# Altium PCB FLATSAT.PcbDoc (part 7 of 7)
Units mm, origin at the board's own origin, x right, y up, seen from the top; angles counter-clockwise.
Board outline 430 x 350 mm, 5 copper layers (Top Layer, Internal Plane 1, Internal Plane 2, DELETEME, Bottom Layer); 808 components, 852 nets, 6407 pads, 939 vias.
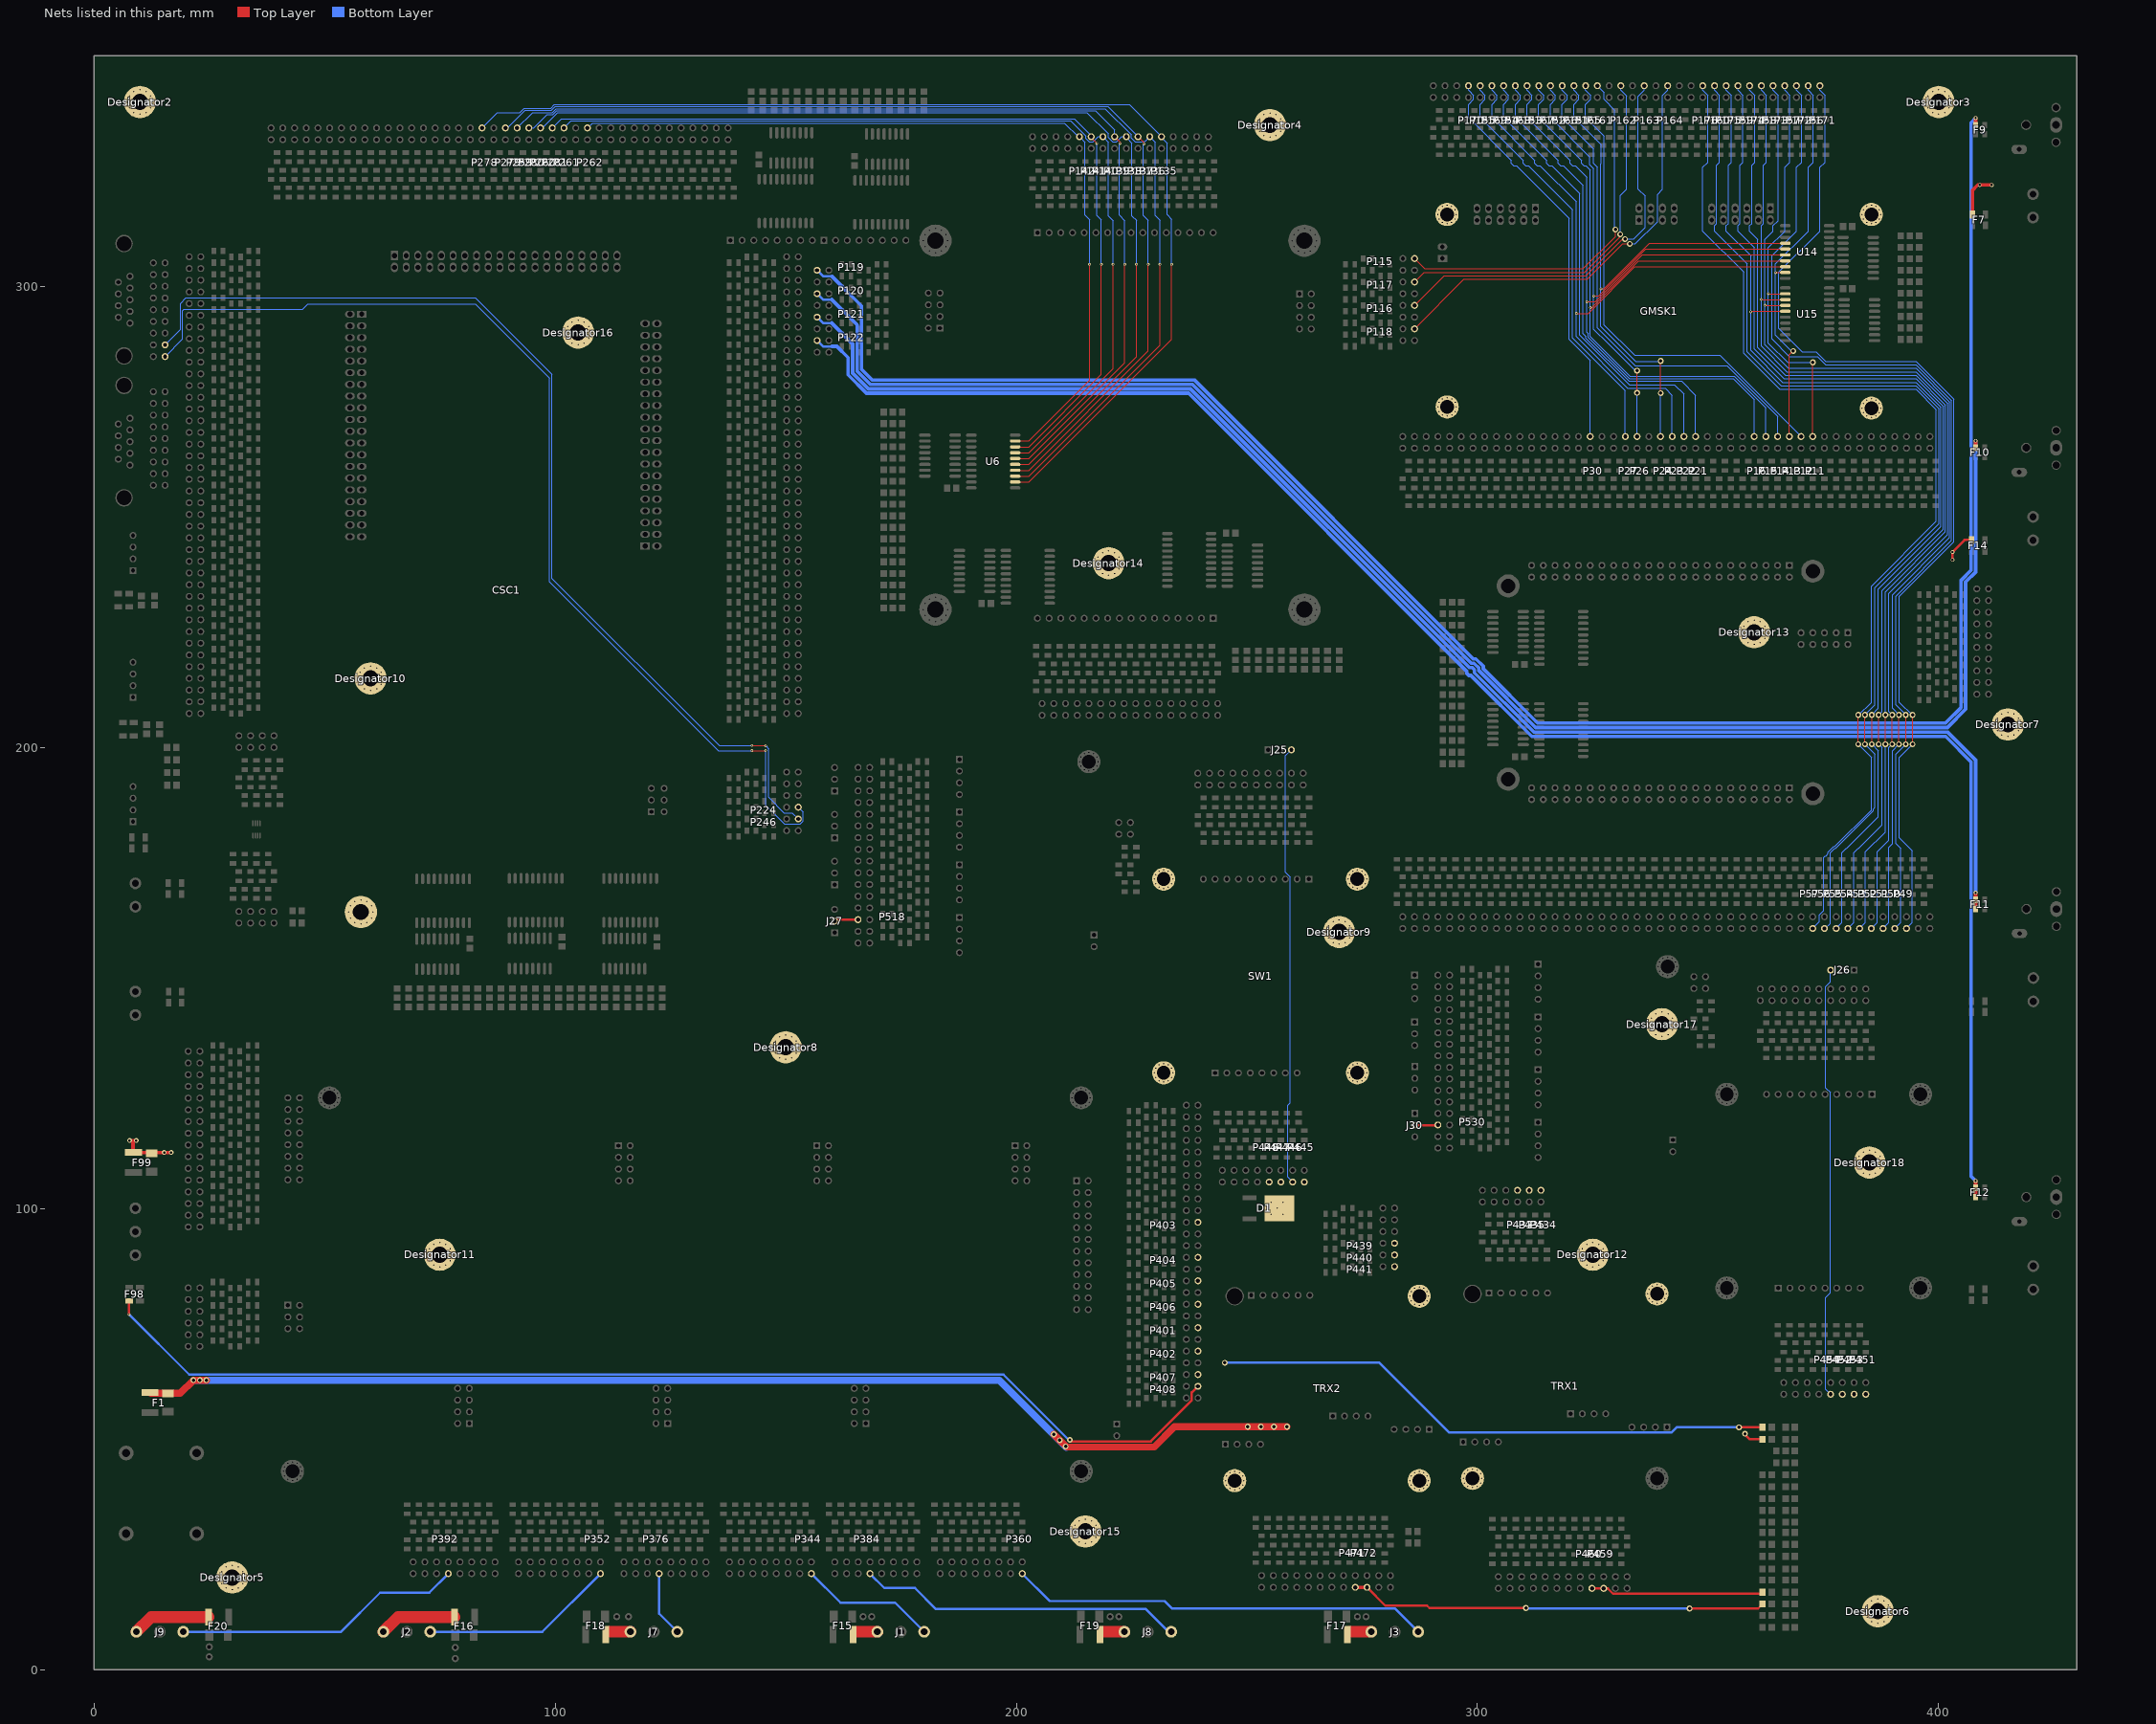
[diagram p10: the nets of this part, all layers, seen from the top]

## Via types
v1: diameter 1.016, hole 0.508, Top Layer to Bottom Layer, 541 vias
v2: diameter 0.6, hole 0.3, Top Layer to Bottom Layer, 214 vias
v3: diameter 1.27, hole 0.711, Top Layer to Bottom Layer, 147 vias
v4: diameter 0.8, hole 0.5, Top Layer to Bottom Layer, 31 vias
v5: diameter 0.5, hole 0.3, Top Layer to Bottom Layer, tented bottom, 5 vias
v6: diameter 1.27, hole 0.635, Top Layer to Bottom Layer, tented both sides, 1 vias

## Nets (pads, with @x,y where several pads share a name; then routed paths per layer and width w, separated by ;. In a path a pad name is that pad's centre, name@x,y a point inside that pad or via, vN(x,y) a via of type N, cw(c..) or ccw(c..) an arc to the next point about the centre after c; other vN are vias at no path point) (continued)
NewNet16: TRX1.@296.927,41.499 TRX1.@297.195,40.499 TRX1.@297.195,42.499 TRX1.@297.927,39.767 TRX1.@297.927,43.231 TRX1.@298.927,39.499 TRX1.@298.927,41.499 TRX1.@298.927,43.499 TRX1.@299.927,39.767 TRX1.@299.927,43.231 TRX1.@300.659,40.499 TRX1.@300.659,42.499 TRX1.@300.927,41.499
NewNet17: TRX1.@336.927,81.499 TRX1.@337.195,80.499 TRX1.@337.195,82.499 TRX1.@337.927,79.767 TRX1.@337.927,83.231 TRX1.@338.927,79.499 TRX1.@338.927,81.499 TRX1.@338.927,83.499 TRX1.@339.927,79.767 TRX1.@339.927,83.231 TRX1.@340.659,80.499 TRX1.@340.659,82.499 TRX1.@340.927,81.499
NewNet18: TRX2.@285.365,41.007 TRX2.@285.633,40.007 TRX2.@285.633,42.007 TRX2.@286.365,39.275 TRX2.@286.365,42.739 TRX2.@287.365,39.007 TRX2.@287.365,41.007 TRX2.@287.365,43.007 TRX2.@288.365,39.275 TRX2.@288.365,42.739 TRX2.@289.097,40.007 TRX2.@289.097,42.007 TRX2.@289.365,41.007
NewNet19: TRX2.@245.365,41.007 TRX2.@245.633,40.007 TRX2.@245.633,42.007 TRX2.@246.365,39.275 TRX2.@246.365,42.739 TRX2.@247.365,39.007 TRX2.@247.365,41.007 TRX2.@247.365,43.007 TRX2.@248.365,39.275 TRX2.@248.365,42.739 TRX2.@249.097,40.007 TRX2.@249.097,42.007 TRX2.@249.365,41.007
NewNet20: TRX2.@285.365,81.007 TRX2.@285.633,80.007 TRX2.@285.633,82.007 TRX2.@286.365,79.275 TRX2.@286.365,82.739 TRX2.@287.365,79.007 TRX2.@287.365,81.007 TRX2.@287.365,83.007 TRX2.@288.365,79.275 TRX2.@288.365,82.739 TRX2.@289.097,80.007 TRX2.@289.097,82.007 TRX2.@289.365,81.007
NewNet21: CSC1.
NewNet22: GMSK1.@291.398,315.61 GMSK1.@291.666,314.61 GMSK1.@291.666,316.61 GMSK1.@292.398,313.878 GMSK1.@292.398,317.342 GMSK1.@293.398,313.61 GMSK1.@293.398,315.61 GMSK1.@293.398,317.61 GMSK1.@294.398,313.878 GMSK1.@294.398,317.342 GMSK1.@295.13,314.61 GMSK1.@295.13,316.61 GMSK1.@295.398,315.61
NewNet23: GMSK1.@291.428,273.87 GMSK1.@291.696,272.87 GMSK1.@291.696,274.87 GMSK1.@292.428,272.138 GMSK1.@292.428,275.602 GMSK1.@293.428,271.87 GMSK1.@293.428,273.87 GMSK1.@293.428,275.87 GMSK1.@294.428,272.138 GMSK1.@294.428,275.602 GMSK1.@295.16,272.87 GMSK1.@295.16,274.87 GMSK1.@295.428,273.87
NewNet24: GMSK1.@383.398,273.61 GMSK1.@383.666,272.61 GMSK1.@383.666,274.61 GMSK1.@384.398,271.878 GMSK1.@384.398,275.342 GMSK1.@385.398,271.61 GMSK1.@385.398,273.61 GMSK1.@385.398,275.61 GMSK1.@386.398,271.878 GMSK1.@386.398,275.342 GMSK1.@387.13,272.61 GMSK1.@387.13,274.61 GMSK1.@387.398,273.61
NewNet25: GMSK1.@383.398,315.61 GMSK1.@383.666,314.61 GMSK1.@383.666,316.61 GMSK1.@384.398,313.878 GMSK1.@384.398,317.342 GMSK1.@385.398,313.61 GMSK1.@385.398,315.61 GMSK1.@385.398,317.61 GMSK1.@386.398,313.878 GMSK1.@386.398,317.342 GMSK1.@387.13,314.61 GMSK1.@387.13,316.61 GMSK1.@387.398,315.61
NewNet26: SW1.@229.956,171.459 SW1.@230.224,170.459 SW1.@230.224,172.459 SW1.@230.956,169.727 SW1.@230.956,173.191 SW1.@231.956,169.459 SW1.@231.956,171.459 SW1.@231.956,173.459 SW1.@232.956,169.727 SW1.@232.956,173.191 SW1.@233.688,170.459 SW1.@233.688,172.459 SW1.@233.956,171.459
NewNet27: SW1.@229.956,129.459 SW1.@230.224,128.459 SW1.@230.224,130.459 SW1.@230.956,127.727 SW1.@230.956,131.191 SW1.@231.956,127.459 SW1.@231.956,129.459 SW1.@231.956,131.459 SW1.@232.956,127.727 SW1.@232.956,131.191 SW1.@233.688,128.459 SW1.@233.688,130.459 SW1.@233.956,129.459
NewNet28: SW1.@271.956,129.459 SW1.@272.224,128.459 SW1.@272.224,130.459 SW1.@272.956,127.727 SW1.@272.956,131.191 SW1.@273.956,127.459 SW1.@273.956,129.459 SW1.@273.956,131.459 SW1.@274.956,127.727 SW1.@274.956,131.191 SW1.@275.688,128.459 SW1.@275.688,130.459 SW1.@275.956,129.459
NewNet29: SW1.@271.956,171.459 SW1.@272.224,170.459 SW1.@272.224,172.459 SW1.@272.956,169.727 SW1.@272.956,173.191 SW1.@273.956,169.459 SW1.@273.956,171.459 SW1.@273.956,173.459 SW1.@274.956,169.727 SW1.@274.956,173.191 SW1.@275.688,170.459 SW1.@275.688,172.459 SW1.@275.956,171.459
NewNet30: Designator2.1
NewNet31: Designator3.1
NewNet32: Designator4.1
NewNet33: Designator5.1
NewNet34: Designator6.1
NewNet35: Designator7.1
NewNet36: Designator8.1
NewNet37: Designator9.1
NewNet38: Designator10.1
NewNet39: Designator11.1
NewNet40: Designator12.1
NewNet41: Designator13.1
NewNet42: Designator14.1
NewNet43: Designator15.1
NewNet44: Designator16.1
NewNet45: Designator17.1
NewNet46: Designator18.1
PLLACQ1: P30.1 P170.1 | length 88.3
  Bottom Layer w0.254: P170.1@298.048,343.53 298.048,342.518 299.128,341.437 299.128,340.543 298.048,339.462 298.048,336.62 307.37,327.298 307.37,326.673 307.861,326.182 308.486,326.182 319.866,314.802 319.866,288.506 324.438,283.934 P30.1@324.438,267.445
PLLACQ2: P57.1 P176.1 | length 235.6
  Top Layer w0.254: v3(382.553,200.73) v3(382.553,207.08)
  Bottom Layer w0.254: P176.1@348.848,343.53 348.848,342.518 349.928,341.437 349.928,326.915 348.848,325.835 348.848,311.982 357.738,303.092 357.738,285.493 365.539,277.692 395.05,277.692 399.466,273.276 399.466,249.088 385.398,235.02 385.398,209.874 385.398,209.817 382.661,207.08 v3(382.553,207.08) ; P57.1@372.698,160.765 374.183,162.25 374.183,163.742 375.103,164.662 375.103,176.185 375.38,176.462 375.575,176.462 376.051,176.938 376.051,177.308 377.262,178.52 377.438,178.52 385.398,186.48 385.398,197.885 v3(382.553,200.73)
PWR_E\N\: J27.2 P518.1 | length 5.1
  Top Layer w0.508: J27.2@160.608,162.67 P518.1@165.688,162.67
RX1_AF: F11.2 P121.1 | length 327.3
  Top Layer w0.762: F11.2@408,165 F11.2@408,167 v4(408,168.509)
  Bottom Layer w0.508: P121.1@156.822,293.352 158.092,292.082 159.979,292.082
  Bottom Layer w0.762: 159.979,292.082 164.52,287.542 164.52,281.21 167.936,277.794 237.786,277.794 298.221,217.359 298.856,217.359 299.359,216.856 299.359,216.221 312.208,203.372 401.898,203.372 408,197.269 v4(408,168.509)
RX1_GMSK: P117.1 P162.1 | length 82.5
  Top Layer w0.254: P117.1@286.362,300.972 288.466,303.076 323.213,303.076 330.948,310.811 v3(330.948,311.314)
  Bottom Layer w0.254: v3(330.948,311.314) 330.948,319.762 332.312,321.126 332.312,341.274 331.068,342.518 P162.1@331.068,343.53
RX2_AF: F12.2 P122.1 | length 385.4
  Top Layer w0.762: F12.2@408,102.5 F12.2@408,104.5 v4(408,106.009)
  Bottom Layer w0.508: P122.1@156.822,288.272 158.092,287.002 159.979,287.002
  Bottom Layer w0.762: 159.979,287.002 161.102,287.002 163.554,284.55 163.554,280.811 167.537,276.828 237.387,276.828 297.641,216.574 297.641,216.144 298.144,215.641 298.574,215.641 311.809,202.406 401.498,202.406 407.035,196.869 407.035,169.723 407.016,169.704 407.016,106.934 ; 407.016,106.993 v4(408,106.009)
RX2_GMSK: P118.1 P164.1 | length 92.9
  Top Layer w0.254: P118.1@286.485,290.69 P118.1@286.362,290.812 297.102,301.552 323.845,301.552 331.523,309.23 v3(333.032,309.23)
  Bottom Layer w0.254: v3(333.032,309.23) 334.206,309.23 339.018,314.042 339.018,319.958 340.148,321.088 340.148,341.437 341.228,342.518 P164.1@341.228,343.53
RX_PSAVE1: P22.1 P154.1 | length 99.3
  Bottom Layer w0.254: P154.1@305.668,343.53 305.668,342.518 306.748,341.437 306.748,340.543 305.668,339.462 305.668,336.62 314.99,327.298 314.99,326.673 315.481,326.182 316.106,326.182 322.152,320.136 322.152,289.453 332.897,278.708 342.726,278.708 344.758,276.676 P22.1@344.758,267.445
RX_PSAVE2: P54.1 P159.1 | length 228
  Top Layer w0.254: v3(386.973,200.73) v3(386.973,207.08)
  Bottom Layer w0.254: P159.1@356.468,343.53 356.468,342.518 357.548,341.437 357.548,326.915 356.938,326.305 356.938,313.663 356.468,313.192 356.468,311.982 360.024,308.426 360.024,286.44 366.486,279.978 395.05,279.978 400.99,274.038 400.99,247.379 387.684,234.073 387.684,207.791 v3(386.973,207.08) ; P54.1@380.318,160.765 381.588,162.035 381.588,177.19 382.511,178.113 382.593,178.113 387.684,183.204 387.684,200.019 v3(386.973,200.73)
RX_S/N1: P15.1 P167.1 U14.7 | length 157.3
  Top Layer w0.152: v2(324.485,295.402) 324.737,295.402 334.895,305.56 U14.7@366.75,305.56
  Bottom Layer w0.254: P167.1@313.288,343.53 313.288,342.518 314.368,341.437 314.368,340.543 313.288,339.462 313.288,336.62 322.61,327.298 322.61,326.673 323.101,326.182 323.486,326.182 324.438,325.229 324.438,289.122 333.074,280.486 355.68,280.486 362.538,273.628 P15.1@362.538,267.445
RX_S/N2: P51.1 P173.1 U15.4 | length 228.7
  Top Layer w0.152: v2@362.371,295.87 U15.4@366.75,295.87
  Top Layer w0.254: v3(391.392,200.73) v3(391.392,207.08)
  Bottom Layer w0.254: P173.1@364.088,343.53 364.088,342.518 365.168,341.437 365.168,314.273 364.088,313.192 364.088,311.982 362.31,310.204 362.31,287.387 367.433,282.264 395.05,282.264 402.361,274.953 402.361,245.518 389.97,233.126 389.97,208.502 v3(391.392,207.08) ; P51.1@387.938,160.765 389.208,162.035 389.208,178.378 389.97,179.14 389.97,199.308 v3(391.392,200.73)
  other v2: 362.331,295.91
RXACQ1: P27.1 P155.1 | length 90.4
  Bottom Layer w0.254: P155.1@300.588,343.53 300.588,342.518 301.668,341.437 301.668,340.543 300.588,339.462 300.588,336.62 309.91,327.298 309.91,326.673 310.401,326.182 311.026,326.182 320.628,316.58 320.628,288.821 332.058,277.391 P27.1@332.058,267.445
RXACQ2: P56.1 P160.1 | length 233.2
  Top Layer w0.254: v3(384.026,200.73) v3(384.026,207.08)
  Bottom Layer w0.254: P160.1@351.388,343.53 351.388,342.518 352.468,341.437 352.468,326.915 351.858,326.305 351.858,313.663 351.388,313.192 351.388,311.982 358.5,304.87 358.5,285.809 365.855,278.454 395.05,278.454 400.075,273.429 400.075,248.62 386.16,234.704 386.16,209.214 v3(384.026,207.08) ; P56.1@375.238,160.765 375.405,160.765 376.508,161.868 376.508,177.154 377.441,178.088 377.616,178.088 385.83,186.301 385.83,186.684 386.16,187.014 386.16,198.596 v3(384.026,200.73)
RXCLK1: P14.1 P166.1 | length 108
  Bottom Layer w0.254: P166.1@318.368,343.53 318.368,342.518 319.448,341.437 319.448,340.543 318.368,339.462 318.368,336.62 325.15,329.838 325.15,326.673 325.962,325.861 325.962,291.031 334.221,282.772 354.156,282.772 365.078,271.85 P14.1@365.078,267.445
RXCLK2: P50.1 P172.1 | length 224.8
  Top Layer w0.254: v3(392.866,200.73) v3(392.866,207.08)
  Bottom Layer w0.254: P172.1@369.168,343.53 369.168,342.518 370.248,341.437 370.248,326.915 369.168,325.835 369.168,311.982 363.834,306.648 363.834,288.588 367.618,284.804 373.714,284.804 375.492,283.026 395.05,283.026 402.819,275.257 402.819,244.897 390.732,232.811 390.732,209.214 v3(392.866,207.08) ; P50.1@390.478,160.765 391.748,162.035 391.748,178.124 390.732,179.14 390.732,198.596 v3(392.866,200.73)
RXDATA1: P26.1 P152.1 U14.5 | length 130.3
  Top Layer w0.152: v2(325.247,297.942) 326.343,297.942 336.501,308.1 U14.5@366.75,308.1
  Top Layer w0.254: v3(334.598,276.93) v3(334.598,281.756)
  Bottom Layer w0.254: P152.1@315.828,343.53 315.828,342.518 316.908,341.437 316.908,340.543 315.828,339.462 315.828,336.62 324.388,328.06 324.388,326.357 325.2,325.545 325.2,290.715 328.156,287.76 v3@334.159,281.756 ; P26.1@334.598,267.445 v3(334.598,276.93)
RXDATA2: P11.1 P157.1 U15.2 | length 89.3
  Top Layer w0.152: v2@363.133,298.41 U15.2@366.75,298.41
  Top Layer w0.254: P11.1@372.698,267.445 v3(372.698,283.534)
  Bottom Layer w0.254: P157.1@366.628,343.53 366.628,342.518 367.708,341.437 367.708,326.915 366.628,325.835 366.628,311.982 363.072,308.426 363.072,287.703 367.241,283.534 v3(372.698,283.534)
  other v2: 363.093,298.45
RXHOLD1: P23.1 P169.1 U14.8 | length 147.8
  Top Layer w0.152: v2(321.437,294.132) 323.998,294.132 329.099,299.232 329.099,299.297 334.092,304.29 U14.8@366.75,304.29
  Bottom Layer w0.254: P169.1@303.128,343.53 303.128,342.518 304.208,341.437 304.208,340.543 303.128,339.462 303.128,336.62 312.45,327.298 312.45,326.673 312.941,326.182 313.566,326.182 321.39,318.358 321.39,289.137 332.581,277.946 340.694,277.946 342.218,276.422 P23.1@342.218,267.445
RXHOLD2: P55.1 P175.1 U15.5 | length 237.9
  Top Layer w0.152: v2@359.35,294.6 U15.5@366.75,294.6
  Top Layer w0.254: v3(385.5,200.73) v3(385.5,207.08)
  Bottom Layer w0.254: P175.1@353.928,343.53 353.928,342.518 355.008,341.437 355.008,326.915 354.398,326.305 354.398,313.663 353.928,313.192 353.928,311.982 359.262,306.648 359.262,286.125 366.171,279.216 395.05,279.216 400.533,273.733 400.533,247.999 386.922,234.389 386.922,208.502 v3(385.5,207.08) ; P55.1@377.778,160.765 379.048,162.035 379.048,177.19 379.971,178.113 380.053,178.113 386.922,184.982 386.922,199.308 v3(385.5,200.73)
  other v2: 359.25,294.5
S0: P135.1 P278.1 U6.2 | length 243.9
  Top Layer w0.152: U6.2@199.75,257.59 202.724,257.59 233.68,288.546 v2(233.68,304.8)
  Bottom Layer w0.152: P135.1@231.482,332.468 231.482,332.248 232.705,331.025 232.705,315.545 233.68,314.57 v2(233.68,304.8)
  Bottom Layer w0.254: P278.1@84.154,334.374 87.52,337.74 92.339,337.74 93.269,338.67 99.093,338.67 99.85,339.427 224.523,339.427 P135.1@231.482,332.468
S1: P136.1 P259.1 U6.3 | length 232.1
  Top Layer w0.152: U6.3@199.75,258.86 202.724,258.86 231.14,287.276 v2(231.14,304.8)
  Bottom Layer w0.152: P136.1@228.942,332.468 230.165,331.246 230.165,315.335 231.14,314.36 v2(231.14,304.8)
  Bottom Layer w0.254: P259.1@91.774,334.374 95.14,337.74 99.384,337.74 100.207,338.564 219.295,338.564 224.943,332.916 224.943,332.154 225.767,331.33 227.223,331.33 227.41,331.516 227.99,331.516 P136.1@228.942,332.468
S2: P137.1 P279.1 U6.4 | length 228.5
  Top Layer w0.152: U6.4@199.75,260.13 202.724,260.13 228.6,286.006 v2(228.6,304.8) ; P137.1@226.402,332.468 227.65,331.221
  Bottom Layer w0.152: v2@227.55,330.911 227.55,315.35 228.6,314.3 v2(228.6,304.8)
  Bottom Layer w0.254: P279.1@89.234,334.374 89.619,334.374 93.458,338.213 99.246,338.213 100.028,338.995 219.875,338.995 P137.1@226.402,332.468
  other v2: 227.66,330.911
S3: P138.1 P260.1 U6.5 | length 216.5
  Top Layer w0.152: U6.5@199.75,261.4 202.724,261.4 226.06,284.736 v2(226.06,304.8)
  Bottom Layer w0.152: P138.1@223.862,332.468 223.862,332.248 225.085,331.025 225.085,315.315 226.06,314.34 v2(226.06,304.8)
  Bottom Layer w0.254: P260.1@96.854,334.374 97.239,334.374 100.565,337.7 215.332,337.7 219.925,333.108 219.925,332.338 220.875,331.388 221.77,331.388 222.85,332.468 P138.1@223.862,332.468
S4: P139.1 P280.1 U6.6 | length 214.3
  Top Layer w0.152: U6.6@199.75,262.67 202.724,262.67 223.52,283.466 v2(223.52,304.8) ; P139.1@221.322,332.468 222.545,331.246 v2(222.545,331.025)
  Bottom Layer w0.152: v2(222.545,331.025) 222.325,330.805 222.325,330.345 222.326,330.344 222.326,329.512 222.325,329.511 222.325,315.45 223.52,314.255 v2(223.52,304.8)
  Bottom Layer w0.254: P280.1@94.314,334.374 95.326,334.374 98.235,337.283 99.537,337.283 100.386,338.132 217.186,338.132 221.322,333.996 P139.1@221.322,332.468
S5: P140.1 P261.1 U6.7 | length 200.1
  Top Layer w0.152: U6.7@199.75,263.94 202.724,263.94 220.98,282.196 v2(220.98,304.8)
  Bottom Layer w0.152: P140.1@218.782,332.468 220.005,331.246 220.005,315.245 220.98,314.27 v2(220.98,304.8)
  Bottom Layer w0.254: P261.1@101.934,334.374 103.471,335.911 211.787,335.911 215.099,332.6 215.099,332.084 215.795,331.388 216.69,331.388 217.77,332.468 P140.1@218.782,332.468
S6: P141.1 P281.1 U6.8 | length 197.1
  Top Layer w0.152: U6.8@199.75,265.21 202.724,265.21 218.44,280.926 v2(218.44,304.8) ; P141.1@216.242,332.468 216.242,332.248 v2(217.465,331.025)
  Bottom Layer w0.152: v2(217.465,331.025) 217.465,315.435 218.44,314.46 v2(218.44,304.8)
  Bottom Layer w0.254: P281.1@99.394,334.374 101.389,336.369 212.6,336.369 216.242,332.726 P141.1@216.242,332.468
S7: P142.1 P262.1 U6.9 | length 183.7
  Top Layer w0.152: U6.9@199.75,266.48 202.724,266.48 215.9,279.656 v2(215.9,304.8)
  Bottom Layer w0.152: P142.1@213.702,332.468 214.925,331.246 214.925,315.45 215.9,314.475 v2(215.9,304.8)
  Bottom Layer w0.254: P262.1@107.014,334.374 108.094,335.454 210.466,335.454 213.452,332.468 P142.1@213.702,332.468
SOLA_X+_T: J1.3 P344.1 | length 29.7
  Bottom Layer w0.508: P344.1@155.579,20.836 161.886,14.529 173.741,14.529 J1.3@180.04,8.23
SOLA_X+_V: F15.1 J1.1 | length 4.6
  Top Layer w2.54: F15.1@165.283,8.23 J1.1@169.88,8.23
SOLA_X-_T: J7.3 P376.1 | length 14.2
  Bottom Layer w0.508: P376.1@122.559,20.836 122.559,12.158 J7.3@126.487,8.23
SOLA_X-_V: F18.1 J7.1 | length 4.6
  Top Layer w2.54: 111.73,8.23 J7.1@116.327,8.23
SOLA_Y+_T: J2.3 P352.1 | length 42.1
  Bottom Layer w0.508: J2.3@72.934,8.23 97.252,8.23 P352.1@109.859,20.836
SOLA_Y+_V: F16.1 J2.1 | length 16.8
  Top Layer w2.54: J2.1@62.774,8.23 65.974,11.43 F16.1@78.2,11.43
SOLA_Y-_T: J8.3 P384.1 | length 70.5
  Bottom Layer w0.508: P384.1@168.279,20.836 171.386,17.729 178.029,17.729 182.601,13.157 228.092,13.157 233.02,8.23 J8.3@233.594,8.23
SOLA_Y-_V: F19.1 J8.1 | length 4.6
  Top Layer w2.54: F19.1@218.836,8.23 J8.1@223.434,8.23
SOLA_Z+_T: J3.3 P360.1 | length 91.1
  Bottom Layer w0.508: P360.1@201.299,20.836 207.251,14.884 232.156,14.884 233.731,13.31 282.067,13.31 J3.3@287.147,8.23
SOLA_Z+_V: F17.1 J3.1 | length 4.6
  Top Layer w2.54: F17.1@272.39,8.23 J3.1@276.987,8.23
SOLA_Z-_T: J9.3 P392.1 | length 62.7
  Bottom Layer w0.508: J9.3@19.38,8.23 53.594,8.23 62.078,16.713 72.716,16.713 P392.1@76.839,20.836
SOLA_Z-_V: F20.1 J9.1 | length 17
  Top Layer w2.54: J9.1@9.22,8.23 12.421,11.43 F20.1@24.86,11.43
TBATT: F98.1 P408.1 | length 252
  Top Layer w0.508: v2(7.62,77.064) 7.62,79.97 F98.1@7.65,80 ; v6(211.582,49.886) 211.938,49.53 229.16,49.53 238.066,58.436 238.066,60.144 P408.1@239.399,61.476
  Bottom Layer w0.508: v2(7.62,77.064) 20.676,64.008 197.231,64.008 v6@211.43,49.809
TELEM_E\N\: J30.2 P530.1 | length 5
  Top Layer w0.508: J30.2@286.418,118.1 P530.1@291.378,118.1
TX1_AF: F9.1 P119.1 | length 429.2
  Top Layer w0.762: F9.1@408,335 v4(408,336.509)
  Bottom Layer w0.508: P119.1@156.822,303.512 158.092,302.242 159.979,302.242
  Bottom Layer w0.762: 159.979,302.242 166.45,295.771 166.45,282.01 168.736,279.724 238.586,279.724 299.072,219.238 299.634,219.238 301.238,217.634 301.238,217.072 313.008,205.302 401.472,205.302 404.876,208.706 404.876,236.296 407.035,238.455 407.035,261.264 407.016,261.284 407.016,335.524 v4(408,336.509)
TX1_GMSK: P115.1 P161.1 | length 81.7
  Top Layer w0.254: P115.1@286.362,306.052 288.577,303.838 322.898,303.838 329.907,310.847 v3(329.907,312.355)
  Bottom Layer w0.254: P161.1@325.988,343.53 327.448,342.07 327.448,340.543 329.773,338.218 329.773,312.489 v3(329.907,312.355)
TX2_AF: F10.1 P120.1 | length 356.5
  Top Layer w0.762: F10.1@408,265 v4(408,266.509)
  Bottom Layer w0.508: P120.1@156.822,298.432 158.092,297.162 159.979,297.162
  Bottom Layer w0.762: 159.979,297.162 165.485,291.657 165.485,281.61 168.336,278.759 238.186,278.759 298.646,218.299 299.245,218.299 300.299,217.245 300.299,216.646 312.608,204.337 401.872,204.337 405.841,208.306 405.841,235.896 408,238.055 v4(408,266.509)
TX2_GMSK: P116.1 P163.1 | length 89.1
  Top Layer w0.254: P116.1@286.485,295.77 P116.1@286.362,295.892 292.784,302.314 323.529,302.314 331.487,310.272 v3(331.99,310.272)
  Bottom Layer w0.254: v3(331.99,310.272) 333.904,310.272 336.376,312.744 336.376,319.602 334.852,321.126 334.852,341.222 336.148,342.518 P163.1@336.148,343.53
TX_PSAVE1: P21.1 P168.1 | length 100.2
  Bottom Layer w0.254: P168.1@308.208,343.53 308.208,342.518 309.288,341.437 309.288,340.543 308.208,339.462 308.208,336.62 317.53,327.298 317.53,326.673 318.021,326.182 318.646,326.182 322.914,321.914 322.914,289.768 323.524,289.159 323.524,288.743 332.797,279.47 344.25,279.47 347.298,276.422 P21.1@347.298,267.445
TX_PSAVE2: P53.1 P174.1 | length 225.5
  Top Layer w0.254: v3(388.446,200.73) v3(388.446,207.08)
  Bottom Layer w0.254: P174.1@359.008,343.53 359.008,342.518 360.088,341.437 360.088,326.915 359.478,326.305 359.478,313.663 359.008,313.192 359.008,311.982 360.786,310.204 360.786,286.756 366.802,280.74 395.05,280.74 401.447,274.343 401.447,246.758 388.446,233.757 v3(388.446,207.08) ; P53.1@382.858,160.765 384.128,162.035 384.128,177.362 388.446,181.68 v3(388.446,200.73)
TXCLK1: P12.1 P165.1 | length 107.1
  Bottom Layer w0.254: P165.1@323.448,343.53 323.448,342.518 324.528,341.437 324.528,340.543 323.448,339.462 323.448,336.62 327.486,332.582 327.486,291.662 334.109,285.039 352.564,285.039 P12.1@370.158,267.445
TXCLK2: P49.1 P171.1 | length 225.3
  Top Layer w0.254: v3(394.339,200.73) v3(394.339,207.08)
  Bottom Layer w0.254: P171.1@374.248,343.53 374.248,342.518 375.328,341.437 375.328,326.915 374.248,325.835 374.248,311.982 365.358,303.092 365.358,290.874 370.412,285.82 373.46,285.82 375.492,283.788 395.05,283.788 403.276,275.562 403.276,244.598 393.941,235.263 391.494,232.816 391.494,209.817 394.231,207.08 v3(394.339,207.08) ; P49.1@393.018,160.765 394.288,162.035 394.288,177.616 391.494,180.41 391.494,197.885 v3(394.339,200.73)
TXDATA1: P24.1 P151.1 U14.4 | length 132.2
  Top Layer w0.152: v2(326.771,299.466) 327.4,299.466 337.304,309.37 U14.4@366.75,309.37
  Top Layer w0.254: v3(339.725,276.86) v3(339.725,283.845)
  Bottom Layer w0.254: P151.1@320.908,343.53 320.908,342.518 321.988,341.437 321.988,340.543 320.908,339.462 320.908,336.62 326.826,330.702 326.826,326.673 326.724,326.571 326.724,291.346 334.282,283.788 v3@339.678,283.788 ; P24.1@339.678,267.445 v3@339.678,276.93
TXDATA2: P13.1 P156.1 U14.9 | length 84.3
  Top Layer w0.254: v2@364.619,303.02 U14.9@366.75,303.02 ; P13.1@367.618,267.445 367.618,285.164 v3(368.454,286)
  Bottom Layer w0.254: v3(368.454,286) 368,286 367.391,286.609 364.596,289.404 364.596,304.87 371.708,311.982 371.708,325.835 372.788,326.915 372.788,341.437 371.708,342.518 P156.1@371.708,343.53
  other v2: 364.617,303.022
TXEN1: P16.1 P153.1 U14.6 | length 158.2
  Top Layer w0.152: v2(323.723,296.672) 325.54,296.672 335.698,306.83 U14.6@366.75,306.83
  Bottom Layer w0.254: P153.1@310.748,343.53 310.748,342.518 311.828,341.437 311.828,340.543 310.748,339.462 310.748,336.62 320.07,327.298 320.07,326.673 320.561,326.182 321.186,326.182 323.676,323.692 323.676,290.084 323.981,289.779 323.981,288.933 332.935,279.978 355.426,279.978 359.998,275.406 P16.1@359.998,267.445
TXEN2: P52.1 P158.1 U15.3 | length 229.3
  Top Layer w0.152: v2@361.609,297.14 U15.3@366.75,297.14
  Top Layer w0.254: v3(389.919,200.73) v3(389.919,207.08)
  Bottom Layer w0.254: P158.1@361.548,343.53 361.548,342.518 362.628,341.437 362.628,326.915 362.018,326.305 362.018,313.663 361.548,313.192 361.548,287.071 367.117,281.502 395.05,281.502 401.904,274.648 401.904,246.138 389.208,233.442 389.208,207.791 v3(389.919,207.08) ; P52.1@385.398,160.765 386.668,162.035 386.668,177.362 389.208,179.902 389.208,200.019 v3(389.919,200.73)
  other v2: 361.569,297.18
UART0_RX: P186.1 P224.1 | length 229.9
  Top Layer w0.254: v2@142.689,199.319 v2(145.669,199.319)
  Bottom Layer w0.254: P186.1@15.443,284.796 19.25,288.603 19.25,294.75 19.539,295.039 45.289,295.039 46.4,296.15 82.762,296.15 98.75,280.162 98.75,235.946 135.407,199.288 v2@142.672,199.288 ; v2(145.669,199.319) 145.669,187.511 149.747,183.434 153.181,183.434 153.814,184.067 153.814,185.974 P224.1@152.734,187.054
  other v2: 142.672,199.336
UART0_TX: P185.1 P246.1 | length 223.7
  Top Layer w0.254: v2(142.672,200.431) v2@145.652,200.431
  Bottom Layer w0.254: P185.1@15.443,287.336 18.818,290.711 18.818,296.318 20,297.5 82.733,297.5 99.334,280.899 99.334,236.682 135.585,200.431 v2(142.672,200.431) ; v2(145.669,200.414) 146.329,199.754 146.329,189.179 149.657,185.852 151.396,185.852 P246.1@152.734,184.514
V_BATT: F99.2 P401.1 P402.1 P403.1 P404.1 P405.1 P406.1 P407.1 R12.2 | length 135.6
  Top Layer w0.508: v3(356.703,52.585) R12.2@361.803,52.585
  Top Layer w0.762: v1(7.749,114.775) 8.5,114.775 ; v1(9.18,114.775) 8.5,114.775 ; v1(16.764,112.175) v1(15.24,112.175) F99.2@8.6,112.175 8.5,112.275 8.5,114.775
  Bottom Layer w0.508: v3(245.203,66.585) 278.703,66.585 293.854,51.434 342.037,51.434 343.188,52.585 v3(356.703,52.585)
V_LOAD: D1.2 F1.2 J25.3 J26.3 P433.1 P434.1 P435.1 P439.1 P440.1 P441.1 P445.1 P446.1 P447.1 P448.1 P451.1 P452.1 P453.1 P454.1 R13.2 | length 455.9
  Top Layer w0.508: v3(358.003,51.185) 357.903,51.085 359.023,49.965 R13.2@361.803,49.965
  Top Layer w1.524: F1.2@12.197,60.115 12.372,59.94 F1.2@16.097,59.94 18.741,59.94 v3(21.59,62.789) v3(22.987,62.789) v3(24.384,62.789) ; v3(208.151,51.054) v3(209.423,49.782) 210.919,48.285 229.895,48.285 234.315,52.705 v3(250.19,52.705) v3(253.026,52.705) v3(255.863,52.705) v3(258.699,52.705)
  Bottom Layer w0.254: J25.3@259.668,199.5 258.398,198.23 258.398,172.93 259.421,171.906 259.421,122.953 258.842,122.373 258.842,106.838 P446.1@259.922,105.758 ; P454.1@376.564,59.736 375.484,60.817 375.484,80.721 376.508,81.745 376.508,125.17 375.484,126.194 375.484,148.1 376.564,149.18 J26.3@376.564,151.732
  Bottom Layer w1.524: v3(21.59,62.789) v3(22.987,62.789) v3(24.384,62.789) 196.291,62.789 209.361,49.719 v3@210.857,48.223
  other v3: 210.693,48.412
  other v5: 255.283,98.806 257.823,98.806 256.553,100.076 255.283,101.346 257.823,101.346
VVAR_TX1: F7.1 P459.1 P460.1 R25.2 | length 47.6
  Top Layer w0.508: P460.1@324.827,17.64 P459.1@327.367,17.64 328.235,17.64 329.417,16.458 332.936,16.458 332.963,16.485 361.463,16.485 R25.2@361.803,16.825
  Top Layer w0.762: F7.1@407.325,315.6 407.325,320.825 408.5,322 v4(411.5,322)
  Bottom Layer w0.762: P459.1@327.367,17.64 P459.1@327.431,17.704
  other v4: 408.9,322
VVAR_TX2: F14.1 P471.1 P472.1 R27.2 | length 97.5
  Top Layer w0.508: P472.1@276.051,17.874 280.037,13.888 289.07,13.888 289.573,13.385 v3(310.503,13.385) ; v3(346.003,13.285) 360.843,13.285 R27.2@361.803,14.245 ; v4(403,240.7) v4(403,242.4) 405.6,245 F14.1@407.15,245
  Top Layer w0.762: P471.1@273.511,17.874 P472.1@276.051,17.874
  Bottom Layer w0.508: v3@310.803,13.685 v3(310.503,13.385) 310.603,13.285 v3@345.603,13.285
pads on no net: BBONE1.M1 BBONE1.M2 BBONE1.M3 BBONE1.M4 F99.3 J19.0 J20.0 J21.0 J22.0 P7.1 P8.1 P9.1 P10.1 P25.1 P28.1 P29.1 P31.1 P32.1 P33.1 P34.1 P35.1 P36.1 P37.1 P38.1 P39.1 P40.1 P41.1 P42.1 P73.1 P74.1 P75.1 P76.1 P77.1 P78.1 P79.1 P80.1 P81.1 P82.1 P83.1 P84.1 P85.1 P86.1 P87.1 P88.1 P89.1 P90.1 P91.1 P92.1 P93.1 P94.1 P95.1 P96.1 P97.1 P98.1 P99.1 P100.1 P101.1 P102.1 P205.1 P212.1 P214.1 P216.1 P217.1 P218.1 P221.1 P222.1 P227.1 P235.1 P239.1 P240.1 P241.1 P243.1 P244.1 P251.1 P255.1 P256.1 P257.1 P258.1 P263.1 P264.1 P265.1 P266.1 P267.1 P268.1 P269.1 P270.1 P274.1 P275.1 P276.1 P277.1 P282.1 P283.1 P284.1 P285.1 P286.1 P287.1 P294.1 P295.1 P304.1 P305.1 P306.1 P307.1 P308.1 P309.1 P310.1 P311.1 P312.1 P317.1 P318.1 P327.1 P328.1 P329.1 P330.1 P331.1 P332.1 P333.1 P334.1 P335.1 P413.1 P414.1 P450.1 P456.1 P519.1 P522.1 P525.1 P528.1 P531.1 P534.1 P537.1 P540.1 TRX1.@298.927,81.499 TRX2.@247.365,81.007 U17.9 U19.10 U23.9

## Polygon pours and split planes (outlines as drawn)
5V0_BBONE on Internal Plane 1 (split plane): 394.49,277.964 394.49,156.729 300.613,156.729 300.513,156.719 300.417,156.69 300.329,156.643 300.252,156.579 300.188,156.502 300.141,156.414 300.112,156.318 300.102,156.218 300.102,138.502 279.533,138.502 279.533,150.376 279.533,150.572 279.533,204.032 279.533,282.454 394.49,282.454
3V3_COMMS on Internal Plane 1 (split plane): 394.49,283.475 279.023,283.475 278.923,283.465 278.827,283.436 278.739,283.389 278.662,283.325 278.598,283.248 278.551,283.16 278.522,283.064 278.512,282.964 278.512,204.032 278.512,202.764 172.038,202.764 171.938,202.755 171.843,202.726 171.754,202.678 171.677,202.615 171.614,202.538 171.566,202.449 171.537,202.354 171.528,202.254 171.528,183.5 157.308,183.5 157.308,344.49 394.49,344.49
5V0_UNREG on Internal Plane 1 (split plane): 384.54,108.57 301.152,108.57 301.152,118.1 301.152,133.166 301.143,133.266 301.123,133.33 301.123,137.992 301.114,138.088 301.123,138.184 301.123,155.708 384.54,155.708
3V3_UNREG on Internal Plane 1 (split plane): 278.512,150.887 172.599,150.887 172.599,172.83 172.589,172.93 172.56,173.025 172.548,173.048 172.548,201.744 278.512,201.744
3V3_CSC on Internal Plane 1 (split plane): 56.076,308.667 56.076,306.076 58.667,306.076 58.743,306 58.667,305.924 56.076,305.924 56.076,303.333 56,303.257 55.924,303.333 55.924,305.924 53.308,305.924 53.308,305.949 53.257,306 53.333,306.076 55.924,306.076 55.924,308.667 56,308.743
V_LOAD on Internal Plane 1 (split plane): 342.776,103.767 342.776,101.176 345.367,101.176 345.443,101.1 345.367,101.024 342.776,101.024 342.776,98.433 342.7,98.357 342.624,98.433 342.624,101.024 340.008,101.024 340.008,101.049 339.957,101.1 340.033,101.176 342.624,101.176 342.624,103.767 342.7,103.843
VVAR_TX1 on Internal Plane 1 (split plane): 414.49,277.454 414.49,13.51 318.987,13.51 318.987,17.64 318.987,20.18 318.987,30.064 405,30.064 405.1,30.073 405.195,30.102 405.284,30.15 405.361,30.213 405.424,30.29 405.472,30.379 405.501,30.474 405.51,30.574 405.51,56 405.51,282.964 405.51,344.49 414.49,344.49
VVAR_TX2 on Internal Plane 1 (split plane): 404.49,282.964 404.49,282.829 404.49,56 404.49,55.921 404.49,31.084 291.291,31.084 291.191,31.075 291.096,31.046 291.007,30.998 290.93,30.935 290.867,30.858 290.819,30.769 290.79,30.674 290.781,30.574 290.781,16.288 267.671,16.288 267.671,17.874 267.671,40.224 395,40.224 395.1,40.233 395.195,40.262 395.284,40.31 395.361,40.373 395.424,40.45 395.472,40.539 395.501,40.634 395.51,40.734 395.51,53.5 395.51,277.964 395.51,344.49 404.49,344.49
8V0_RX1 on Internal Plane 1 (split plane): 424.49,5.51 291.801,5.51 291.801,10.254 291.801,30.064 317.966,30.064 317.966,20.18 317.966,17.64 317.966,13 317.976,12.9 318.005,12.805 318.052,12.716 318.116,12.639 318.193,12.576 318.281,12.528 318.377,12.499 318.477,12.49 415,12.49 415.1,12.499 415.195,12.528 415.284,12.576 415.361,12.639 415.424,12.716 415.472,12.805 415.501,12.9 415.51,13 415.51,277.454 415.51,344.49 424.49,344.49
8V0_RX2 on Internal Plane 1 (split plane): 394.49,53.5 394.49,41.244 267.161,41.244 267.061,41.235 266.966,41.206 266.877,41.158 266.8,41.095 266.737,41.018 266.689,40.929 266.66,40.834 266.651,40.734 266.651,17.874 266.651,16.288 243.668,16.288 243.668,23.99 243.659,24.089 243.651,24.115 243.659,24.14 243.668,24.24 243.668,49.13 385.05,49.13 385.15,49.139 385.245,49.168 385.334,49.216 385.411,49.279 385.474,49.356 385.522,49.445 385.551,49.54 385.56,49.64 385.56,155.708 394.49,155.708
V_LOAD on Internal Plane 1 (split plane): 384.54,50.15 248.748,50.15 248.748,107.55 384.54,107.55
5V0_AUX on Internal Plane 1 (split plane): 278.512,137.992 278.522,137.892 278.551,137.797 278.598,137.708 278.662,137.631 278.739,137.568 278.827,137.52 278.923,137.491 279.023,137.482 300.102,137.482 300.102,128.85 269.068,128.85 269.068,138.5 269.059,138.6 269.03,138.695 268.982,138.784 268.919,138.861 268.842,138.924 268.753,138.972 268.658,139.001 268.558,139.01 15.51,139.01 15.51,149.866 278.512,149.866
5V0_TELEM on Internal Plane 1 (split plane): 14.49,128.34 14.499,128.24 14.528,128.145 14.576,128.056 14.639,127.979 14.716,127.916 14.805,127.868 14.9,127.839 15,127.83 257.888,127.83 257.888,118.1 257.897,118 257.926,117.905 257.974,117.816 258.037,117.739 258.114,117.676 258.203,117.628 258.298,117.599 258.398,117.59 300.132,117.59 300.132,108.57 248.748,108.57 248.748,118.18 248.739,118.28 248.71,118.375 248.662,118.464 248.599,118.541 248.522,118.604 248.433,118.652 248.338,118.681 248.238,118.69 5.51,118.69 5.51,344.49 14.49,344.49
5V0_BCR on Internal Plane 1 (split plane): 268.048,128.34 268.057,128.24 268.086,128.145 268.134,128.056 268.197,127.979 268.274,127.916 268.363,127.868 268.458,127.839 268.558,127.83 300.132,127.83 300.132,118.61 258.908,118.61 258.908,128.34 258.899,128.44 258.87,128.535 258.822,128.624 258.759,128.701 258.682,128.764 258.593,128.812 258.498,128.841 258.398,128.85 15.51,128.85 15.51,137.99 268.048,137.99
3V3_AUX on Internal Plane 1 (split plane): 171.578,162.825 15.51,162.825 15.51,172.32 171.578,172.32
3V3_CSC on Internal Plane 1 (split plane): 156.288,182.99 156.297,182.89 156.326,182.795 156.374,182.706 156.437,182.629 156.514,182.566 156.603,182.518 156.698,182.489 156.798,182.48 171.528,182.48 171.528,173.34 15.51,173.34 15.51,344.49 156.288,344.49
3V3_PWR on Internal Plane 1 (split plane): 171.578,150.887 15.51,150.887 15.51,161.804 171.578,161.804
V_BATT on Internal Plane 1 (split plane): 247.728,108.204 247.728,108.06 247.728,50.15 228.01,50.15 228.01,97.5 228.001,97.6 227.972,97.695 227.924,97.784 227.861,97.861 227.784,97.924 227.695,97.972 227.6,98.001 227.5,98.01 5.51,98.01 5.51,117.67 247.728,117.67
GND on Internal Plane 1 (split plane): 429.49,0.51 0.51,0.51 0.51,349.49 429.49,349.49
GND on Internal Plane 1 (split plane): 59.881,25.239 35.119,25.239 35.119,34.761 59.881,34.761
GND on Internal Plane 1 (split plane): 32.576,47.167 32.576,44.576 35.167,44.576 35.243,44.5 35.167,44.424 32.576,44.424 32.576,41.833 32.5,41.757 32.424,41.833 32.424,44.424 29.808,44.424 29.808,44.449 29.757,44.5 29.833,44.576 32.424,44.576 32.424,47.167 32.5,47.243
GND on Internal Plane 1 (split plane): 46.408,32.692 46.408,31.016 42.217,26.825 42.217,26.8 45.951,26.8 46.408,26.342 46.408,25.936 46.001,25.53 40.464,25.53 40.058,25.936 40.058,26.419 45.138,31.499 45.138,32.261 44.249,33.15 42.242,33.15 40.972,31.88 40.439,31.88 40.083,32.235 40.083,32.794 41.709,34.42 44.681,34.42
GND on Internal Plane 2 (split plane): 342.776,103.767 342.776,101.176 345.367,101.176 345.443,101.1 345.367,101.024 342.776,101.024 342.776,98.433 342.7,98.357 342.624,98.433 342.624,101.024 340.008,101.024 340.008,101.049 339.957,101.1 340.033,101.176 342.624,101.176 342.624,103.767 342.7,103.843
GND on Internal Plane 2 (split plane): 56.076,308.667 56.076,306.076 58.667,306.076 58.743,306 58.667,305.924 56.076,305.924 56.076,303.333 56,303.257 55.924,303.333 55.924,305.924 53.308,305.924 53.308,305.949 53.257,306 53.333,306.076 55.924,306.076 55.924,308.667 56,308.743
GND on Internal Plane 2 (split plane): 53.215,32.794 53.215,31.016 52.199,30 53.215,28.984 53.215,27.206 51.564,25.555 48.516,25.555 46.865,27.206 46.865,27.714 47.246,28.095 47.754,28.095 49.024,26.825 51.056,26.825 51.945,27.714 51.945,28.476 51.056,29.365 49.786,29.365 49.405,29.746 49.405,30.254 49.786,30.635 51.031,30.635 51.92,31.524 51.945,31.524 51.945,32.286 51.056,33.175 49.024,33.175 47.754,31.905 47.246,31.905 46.865,32.286 46.865,32.794 48.516,34.445 51.564,34.445
GND on Internal Plane 2 (split plane): 59.881,25.239 35.119,25.239 35.119,34.761 59.881,34.761
GND on Internal Plane 2 (split plane): 32.576,47.167 32.576,44.576 35.167,44.576 35.243,44.5 35.167,44.424 32.576,44.424 32.576,41.833 32.5,41.757 32.424,41.833 32.424,44.424 29.808,44.424 29.808,44.449 29.757,44.5 29.833,44.576 32.424,44.576 32.424,47.167 32.5,47.243
GND on Internal Plane 2 (split plane): 429.49,0.51 0.51,0.51 0.51,349.49 429.49,349.49

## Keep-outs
Keep-Out Layer:
  lines w1.016: 0,0 0,346 0,350 430,350 430,0 0,0

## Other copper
Internal Plane 1 (plane layer: these items are gaps in the copper):
  lines w1.016: 4.925,118.18 11.764,118.18 ; 11.137,118.18 248.238,118.18 248.238,108.06 288.918,108.06 300.642,108.06 300.642,118.1 ; 15,138.5 268.558,138.5 268.558,128.34 300.613,128.34 300.613,137.992 279.023,137.992 279.023,150.376 ; 15,150.376 172.089,150.376 ; 15,162.314 172.089,162.314 ; 15,172.83 172.038,172.83 172.038,202.254 279.023,202.254 279.023,282.964 385,282.964 394.964,282.964 ; 15,345 15,128.34 258.398,128.34 258.398,118.1 300.642,118.1 ; 156.798,345 156.798,182.99 172.038,182.99 ; 171.835,172.83 172.089,172.83 172.089,150.376 ; 227.5,49.724 227.5,97.5 207.5,97.5 5,97.5 5,345 425,345 425,5 291.291,5 291.291,10.254 291.291,30.574 354.791,30.574 405,30.574 405,56 ; 227.584,49.64 244.856,49.64 ; 243.158,23.99 243.158,15.777 291.287,15.777 ; 243.158,24.24 243.158,49.64 385.05,49.64 385.05,156.168 ; 248.238,49.974 248.238,108.204 ; 267.161,15.799 267.161,17.874 267.161,40.734 291.291,40.734 354.791,40.734 395,40.734 395,53.5 395,277.964 395,345 ; 279.023,204.032 279.023,150.572 279.023,150.376 ; 300.308,108.06 356.188,108.06 384.94,108.06 385,108 ; 300.613,138.184 300.613,156.218 385,156.218 ; 300.642,133.166 300.642,118.1 ; 318.477,30.34 318.477,20.18 318.477,17.64 318.477,13 340.507,13 415,13 415,277.454 415,345 ; 384.8,156.218 394.982,156.218 ; 405,55.921 405,282.964 ; 405,282.829 405,345 ; 172.089,150.376 278.261,150.376 ; 278.261,150.376 279.023,150.376 ; 278.261,150.376 279.023,150.376

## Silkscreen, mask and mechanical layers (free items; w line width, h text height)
Top Overlay:
  lines w0.254: 51,152 69,152 ; 80,152 89,152 ; 100,152 109,152 ; 121,152 126,152 ; 18,311 18,342 31,342 31,311 18,311
  lines w0.381: 120.65,142.748 120.65,138.938 124.079,138.938 ; 123.19,142.748 123.19,141.351 124.079,141.351
  text "Mitch Wenke" at 19,341 h1.52 r270
  text "Alexis Shaw" at 21,341 h1.52 r270
  text "Ekram-Ul-Islam Nafis" at 23,341 h1.52 r270
  text "Cameron Brown" at 25,341 h1.52 r270
  text "FlatSat PCB" at 28,341 h2.29 r270
  text "BUS" at 3,247 h1.52 r270
  text "PAYLOAD" at 5,247 h1.52 r270
  text "GND" at 10.5,245.5 h1.52
  text "SDA" at 10.5,242.96 h1.52
  text "SCL" at 10.5,240.42 h1.52
  text "3V3" at 10.5,237.88 h1.52
  text "SLAVE BUS" at 3,220 h1.52 r270
  text "PAYLOAD" at 5,220 h1.52 r270
  text "GND" at 10.5,218 h1.52
  text "SDA" at 10.5,215.46 h1.52
  text "SCL" at 10.5,212.92 h1.52
  text "3V3" at 10.5,210.38 h1.52
  text "+" at 259.104,201.254 h1.52
  text "BUS" at 3,192.5 h1.52 r270
  text "TELEM" at 5,192.5 h1.52 r270
  text "GND" at 10.5,191.04 h1.52
  text "+" at 162.64,189.808 h1.52
  text "SDA" at 10.5,188.5 h1.52
  text "SCL" at 10.5,185.96 h1.52
  text "5V0" at 10.5,183.42 h1.52
  text "+" at 162.64,179.648 h1.52
  text "+" at 162.64,169.488 h1.52
  text "+" at 162.64,159.074 h1.52
  text "+" at 376,153.486 h1.52
  text "+" at 288.421,149.868 h1.52
  text "+" at 288.421,139.708 h1.52
  text "+" at 288.45,130.038 h1.52
  text "+" at 288.45,119.878 h1.52
Top Solder:
  rectangle: 34,24 61,36
Bottom Solder:
  rectangle: 34,24 61,36
Mechanical 1:
  drawing of 356 lines, arcs and shapes, not listed
  text "IPC-6012 Class 2 Except as below" at 443.75,137.5 h2.29
  text "Core Material In Accordance with IPC-4101/26" at 443.75,127.5 h2.29
  text "Pre-Preg Material In Accordance with IPC-4101/26" at 443.75,122.5 h2.29
  text "Maximum bow and twist shall not exceed +/- 0.010\"[.254mm] per inch." at 443.75,112.5 h2.29
  text "All exposed copper areas shall be covered with ENIG" at 443.75,102.5 h2.29
  text "Board Shall be solder masked, both sides," at 443.75,92.5 h2.29
  text "using liquid photo-imageable material (LPI)." at 443.75,87.5 h2.29
  text "Materail shall be Black in color." at 443.75,82.5 h2.29
  text "Registration shall not exceed +/- 0.003\"" at 443.75,77.5 h2.29
  text "Solder mask shall be placed over bare copper" at 443.75,72.5 h2.29
  text "Layer Stack Up as follows:" at 443.75,62.5 h2.29
  text "LAYER" at 510,55 h2.29
  text "MATERIAL" at 526.25,55 h2.29
  text "Thickness" at 553.75,55 h2.29
  text "GTO" at 512.5,50 h2.29
  text "GTS" at 512.5,46.25 h2.29
  text "Plating" at 526.25,42.5 h2.29
  text "0.0007 in" at 553.75,42.5 h2.29
  text "GTL" at 512.5,41.25 h2.29
  text "Copper" at 526.25,40 h2.29
  text "0.0007 in" at 553.75,40 h2.29
  text "Pre-Preg" at 526.25,36.25 h2.29
  text "GP1" at 512.5,32.5 h2.29
  text "Copper" at 526.25,32.5 h2.29
  text "0.0007 in" at 553.75,32.5 h2.29
  text "Core" at 526.25,27.5 h2.29
  text "GP2" at 512.5,22.5 h2.29
  text "Copper" at 526.25,22.5 h2.29
  text "0.0007 in" at 553.75,22.5 h2.29
  text "Pre-Preg" at 526.25,18.75 h2.29
  text "Copper" at 526.25,15 h2.29
  text "0.0007 in" at 553.75,15 h2.29
  text "GBL" at 512.5,13.75 h2.29
  text "Plating" at 526.25,12.5 h2.29
  text "0.0007 in" at 553.75,12.5 h2.29
  text "GBS" at 512.5,8.75 h2.29
  text "GBO" at 512.5,5 h2.29
  text "TOTAL" at 538.75,-2.5 h2.29
  text "0.062 in (+/- 0.010 in)" at 553.75,-2.5 h2.29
